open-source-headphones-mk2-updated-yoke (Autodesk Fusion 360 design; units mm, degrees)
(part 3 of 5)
sketch "Sketch1" plane through (0, 0, 1.5) normal (0, 0, 1) x axis (-1, 0, 0)
  line L1 (-6.5, -117.4019) -> (-9.9868, -115.3888)
  line L2 (-1, -130.9545) -> (-1, -126.9282)
  line L3 (-1, -107.0385) -> (-1, -103.0294)
  line L4 (-14.1969, -110.6487) -> (-10.725, -112.6532)
  line L5 (5.5, -115.6699) -> (8.9868, -113.6567)
  line L6 (-8.9868, -113.6567) -> (-5.5, -115.6699)
  line L7 (1, -132.9615) -> (1, -136.9706)
  line L8 (14.1969, -129.3513) -> (10.725, -127.3468)
  line L9 (11.725, -125.6147) -> (15.1969, -127.6193)
  line L10 (15.1969, -112.3807) -> (11.725, -114.3853)
  line L11 (-11.725, -114.3853) -> (-15.1969, -112.3807)
  line L12 (-15.1969, -127.6193) -> (-11.725, -125.6147)
  line L13 (-10.725, -127.3468) -> (-14.1969, -129.3513)
  line L14 (-1, -136.9706) -> (-1, -132.9615)
  line L15 (10.725, -112.6532) -> (14.1969, -110.6487)
  line L16 (1, -103.0294) -> (1, -107.0385)
  line L17 (1, -126.9282) -> (1, -130.9545)
  line L18 (9.9868, -115.3888) -> (6.5, -117.4019)
  line L19 (-16.1795, -137.7263) -> (-12.9621, -133.8919)
  line L20 (-11.43, -135.1775) -> (-14.6475, -139.0119)
  line L21 (-1, -143.9792) -> (-1, -138.9737)
  line L22 (1, -138.9737) -> (1, -143.9792)
  line L23 (14.6475, -139.0119) -> (11.43, -135.1775)
  line L24 (12.9621, -133.8919) -> (16.1795, -137.7263)
  line L25 (23.4412, -125.1487) -> (18.5118, -124.2796)
  line L26 (18.8591, -122.3099) -> (23.7885, -123.1791)
  line L27 (21.2666, -108.8764) -> (16.9317, -111.3792)
  line L28 (15.9317, -109.6471) -> (20.2666, -107.1444)
  line L29 (9.141, -97.809) -> (7.4291, -102.5126)
  line L30 (5.5497, -101.8286) -> (7.2617, -97.1249)
  line L31 (-7.2617, -97.1249) -> (-5.5497, -101.8286)
  line L32 (-7.4291, -102.5126) -> (-9.141, -97.809)
  line L33 (-20.2666, -107.1444) -> (-15.9317, -109.6471)
  line L34 (-16.9317, -111.3792) -> (-21.2666, -108.8764)
  line L35 (-23.7885, -123.1791) -> (-18.8591, -122.3099)
  line L36 (-18.5118, -124.2796) -> (-23.4412, -125.1487)
  arc A1 centre (0, -120) radius 7 clockwise from (-1, -126.9282) to (-6.5, -117.4019)
  arc A2 centre (0, -120) radius 11 clockwise from (-1, -130.9545) to (-9.9868, -115.3888)
  arc A3 centre (0, -120) radius 13 clockwise from (-10.725, -112.6532) to (-1, -107.0385)
  arc A4 centre (0, -120) radius 17 clockwise from (-14.1969, -110.6487) to (-1, -103.0294)
  circle C1 centre (0, -120) radius 5
  arc A5 centre (0, -120) radius 7 clockwise from (-5.5, -115.6699) to (5.5, -115.6699)
  arc A6 centre (0, -120) radius 11 clockwise from (-8.9868, -113.6567) to (8.9868, -113.6567)
  arc A7 centre (0, -120) radius 13 clockwise from (10.725, -127.3468) to (1, -132.9615)
  arc A8 centre (0, -120) radius 17 clockwise from (14.1969, -129.3513) to (1, -136.9706)
  arc A9 centre (0, -120) radius 17 clockwise from (15.1969, -112.3807) to (15.1969, -127.6193)
  arc A10 centre (0, -120) radius 13 clockwise from (11.725, -114.3853) to (11.725, -125.6147)
  arc A11 centre (0, -120) radius 17 clockwise from (-15.1969, -127.6193) to (-15.1969, -112.3807)
  arc A12 centre (0, -120) radius 13 clockwise from (-11.725, -125.6147) to (-11.725, -114.3853)
  arc A13 centre (0, -120) radius 17 clockwise from (-1, -136.9706) to (-14.1969, -129.3513)
  arc A14 centre (0, -120) radius 13 clockwise from (-1, -132.9615) to (-10.725, -127.3468)
  arc A15 centre (0, -120) radius 17 clockwise from (1, -103.0294) to (14.1969, -110.6487)
  arc A16 centre (0, -120) radius 13 clockwise from (1, -107.0385) to (10.725, -112.6532)
  arc A17 centre (0, -120) radius 7 clockwise from (6.5, -117.4019) to (1, -126.9282)
  arc A18 centre (0, -120) radius 11 clockwise from (9.9868, -115.3888) to (1, -130.9545)
  arc A19 centre (0, -120) radius 19 clockwise from (-12.9621, -133.8919) to (-18.5118, -124.2796)
  arc A20 centre (0, -120) radius 24 clockwise from (-14.6475, -139.0119) to (-16.1795, -137.7263)
  arc A21 centre (0, -120) radius 19 clockwise from (-1, -138.9737) to (-11.43, -135.1775)
  arc A22 centre (0, -120) radius 24 clockwise from (1, -143.9792) to (-1, -143.9792)
  arc A23 centre (0, -120) radius 19 clockwise from (11.43, -135.1775) to (1, -138.9737)
  arc A24 centre (0, -120) radius 24 clockwise from (16.1795, -137.7263) to (14.6475, -139.0119)
  arc A25 centre (0, -120) radius 19 clockwise from (18.5118, -124.2796) to (12.9621, -133.8919)
  arc A26 centre (0, -120) radius 24 clockwise from (23.7885, -123.1791) to (23.4412, -125.1487)
  arc A27 centre (0, -120) radius 19 clockwise from (16.9317, -111.3792) to (18.8591, -122.3099)
  arc A28 centre (0, -120) radius 24 clockwise from (20.2666, -107.1444) to (21.2666, -108.8764)
  arc A29 centre (0, -120) radius 19 clockwise from (7.4291, -102.5126) to (15.9317, -109.6471)
  arc A30 centre (0, -120) radius 24 clockwise from (7.2617, -97.1249) to (9.141, -97.809)
  arc A31 centre (0, -120) radius 19 clockwise from (-5.5497, -101.8286) to (5.5497, -101.8286)
  arc A32 centre (0, -120) radius 24 clockwise from (-9.141, -97.809) to (-7.2617, -97.1249)
  arc A33 centre (0, -120) radius 19 clockwise from (-15.9317, -109.6471) to (-7.4291, -102.5126)
  arc A34 centre (0, -120) radius 24 clockwise from (-21.2666, -108.8764) to (-20.2666, -107.1444)
  arc A35 centre (0, -120) radius 19 clockwise from (-18.8591, -122.3099) to (-16.9317, -111.3792)
  arc A36 centre (0, -120) radius 24 clockwise from (-23.4412, -125.1487) to (-23.7885, -123.1791)
  circle C2 centre (0, -120) radius 19
  concentric A1 C2
  dimension "d412" diameter C2 = 38
extrude "Extrude1" cut sketch "Sketch1" profile of L19 A20 L20 L21 A22 L22 L23 A24 L24 L25 A26 L26 L27 A28 L28 L29 A30 L30 L31 A32 L32 L33 A34 L34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 against normal blind 1.5 bodies "Pad Mount (1)"
sketch "Sketch2" plane through (0, 0, 0) normal (0, 0, -1) x axis (1, 0, 0)
  line L1 (9.9868, -115.3888) -> (6.5, -117.4019)
  line L2 (1, -126.9282) -> (1, -130.9545)
  line L3 (1, -103.0294) -> (1, -107.0385)
  line L4 (10.725, -112.6532) -> (14.1969, -110.6487)
  line L5 (-8.9868, -113.6567) -> (-5.5, -115.6699)
  line L6 (5.5, -115.6699) -> (8.9868, -113.6567)
  line L7 (-1, -136.9706) -> (-1, -132.9615)
  line L8 (-10.725, -127.3468) -> (-14.1969, -129.3513)
  line L9 (-11.725, -114.3853) -> (-15.1969, -112.3807)
  line L10 (-15.1969, -127.6193) -> (-11.725, -125.6147)
  line L11 (11.725, -125.6147) -> (15.1969, -127.6193)
  line L12 (15.1969, -112.3807) -> (11.725, -114.3853)
  line L13 (1, -132.9615) -> (1, -136.9706)
  line L14 (14.1969, -129.3513) -> (10.725, -127.3468)
  line L15 (-1, -107.0385) -> (-1, -103.0294)
  line L16 (-14.1969, -110.6487) -> (-10.725, -112.6532)
  line L17 (-1, -130.9545) -> (-1, -126.9282)
  line L18 (-6.5, -117.4019) -> (-9.9868, -115.3888)
  circle C1 centre (0, -120) radius 19
  arc A1 centre (0, -120) radius 11 clockwise from (9.9868, -115.3888) to (1, -130.9545)
  arc A2 centre (0, -120) radius 7 clockwise from (6.5, -117.4019) to (1, -126.9282)
  arc A3 centre (0, -120) radius 17 clockwise from (1, -103.0294) to (14.1969, -110.6487)
  arc A4 centre (0, -120) radius 13 clockwise from (1, -107.0385) to (10.725, -112.6532)
  circle C2 centre (0, -120) radius 5
  arc A5 centre (0, -120) radius 11 clockwise from (-8.9868, -113.6567) to (8.9868, -113.6567)
  arc A6 centre (0, -120) radius 7 clockwise from (-5.5, -115.6699) to (5.5, -115.6699)
  arc A7 centre (0, -120) radius 17 clockwise from (-1, -136.9706) to (-14.1969, -129.3513)
  arc A8 centre (0, -120) radius 13 clockwise from (-1, -132.9615) to (-10.725, -127.3468)
  arc A9 centre (0, -120) radius 17 clockwise from (-15.1969, -127.6193) to (-15.1969, -112.3807)
  arc A10 centre (0, -120) radius 13 clockwise from (-11.725, -125.6147) to (-11.725, -114.3853)
  arc A11 centre (0, -120) radius 17 clockwise from (15.1969, -112.3807) to (15.1969, -127.6193)
  arc A12 centre (0, -120) radius 13 clockwise from (11.725, -114.3853) to (11.725, -125.6147)
  arc A13 centre (0, -120) radius 17 clockwise from (14.1969, -129.3513) to (1, -136.9706)
  arc A14 centre (0, -120) radius 13 clockwise from (10.725, -127.3468) to (1, -132.9615)
  arc A15 centre (0, -120) radius 17 clockwise from (-14.1969, -110.6487) to (-1, -103.0294)
  arc A16 centre (0, -120) radius 13 clockwise from (-10.725, -112.6532) to (-1, -107.0385)
  arc A17 centre (0, -120) radius 11 clockwise from (-1, -130.9545) to (-9.9868, -115.3888)
  arc A18 centre (0, -120) radius 7 clockwise from (-1, -126.9282) to (-6.5, -117.4019)
  circle C3 centre (0, -120) radius 24
  circle C4 centre (0, -120) radius 20.5
  concentric C1 C3
  concentric C1 C4
  dimension "d415" diameter C3 = 48
  dimension "d416" diameter C4 = 41
extrude "Extrude2" add sketch "Sketch2" profile of C3 C4 against normal blind 2.5
extrude "Extrude3" add of existing geometry blind 2.5
extrude "Extrude4" add sketch "Sketch2" profile of C1 C4 against normal blind 2.5 bodies "Pad Mount (1)"
delete_face "DeleteFace1"
extrude "Extrude5" cut of existing geometry blind -4
sketch "Sketch3" plane through (0, 0, 22) normal (0, 0, 1) x axis (-1, 0, 0)
  line L1 (27.3973, -100.8162) -> (24.0432, -103.1648)
  line L2 (24.0432, -136.8352) -> (27.3973, -139.1838)
  line L3 (-8, -87.4692) -> (-8, -96.1036)
  line L4 (8, -96.1036) -> (8, -87.4692)
  line L5 (-27.3973, -139.1838) -> (-24.0432, -136.8352)
  line L6 (-24.0432, -103.1648) -> (-27.3973, -100.8162)
  line L7 (-8, -65.8761) -> (-8, -68.1306)
  line L8 (8, -68.1306) -> (8, -65.8761)
  line L9 (17.2573, -73.968) -> (18.1032, -72.1557)
  line L10 (6, -66.9692) -> (6, -69.7523)
  line L11 (-6, -66.9692) -> (6, -66.9692)
  line L12 (-6, -69.7523) -> (-6, -66.9692)
  line L13 (-18.1032, -72.1557) -> (-17.2573, -73.968)
  line L14 (-15.6326, -145.0174) -> (-17.7523, -148.4096)
  line L15 (17.7523, -148.4096) -> (15.6326, -145.0174)
  line L16 (8, -97) -> (8, -96.1036)
  line L17 (8, -101.1254) -> (8, -97)
  line L18 (-8, -101.1254) -> (-8, -96.1036)
  line L19 (20.5, -120) -> (0, -120)
  line L20 (15.9099, -104.0901) -> (0, -120)
  line L21 (22.5, -120) -> (0, -120)
  line L22 (-15.9099, -104.0901) -> (0, -120)
  line L23 (-22.5, -120) -> (0, -120)
  line L24 (44.7744, -114.5) -> (37, -114.5)
  line L25 (-37, -114.5) -> (-44.7744, -114.5)
  line L26 (-37, -125.5) -> (-37, -114.5)
  line L27 (-44.7744, -125.5) -> (-37, -125.5)
  line L28 (37, -125.5) -> (44.7744, -125.5)
  line L29 (37, -114.5) -> (37, -125.5)
  line L30 (40.4204, -134.6184) -> (31.8667, -135.2833)
  line L31 (40.0904, -135.7159) -> (40.4204, -134.6184)
  line L32 (33.9261, -136.0336) -> (40.0904, -135.7159)
  curve K1 (32.5509, -136.0589) -> (33.9261, -136.0336)
  curve K2 (33.681, -136.8488) -> (32.5509, -136.0589)
  line L33 (38.6244, -140.5917) -> (33.681, -136.8488)
  line L34 (38.3133, -141.6264) -> (38.6244, -140.5917)
  line L35 (31.554, -136.3233) -> (38.3133, -141.6264)
  line L36 (31.8667, -135.2833) -> (31.554, -136.3233)
  line L37 (30.457, -152.0325) -> (25.6804, -148.7507)
  line L38 (29.9007, -152.8421) -> (30.457, -152.0325)
  line L39 (25.1241, -149.5603) -> (29.9007, -152.8421)
  line L40 (25.6804, -148.7507) -> (25.1241, -149.5603)
  line L41 (-27.2839, -159.541) -> (-19.3124, -156.3956)
  line L42 (-28.0551, -158.7007) -> (-27.2839, -159.541)
  line L43 (-24.3746, -150.8793) -> (-28.0551, -158.7007)
  line L44 (-23.5592, -151.7679) -> (-24.3746, -150.8793)
  line L45 (-24.7134, -154.0936) -> (-23.5592, -151.7679)
  line L46 (-22.4517, -156.5582) -> (-24.7134, -154.0936)
  line L47 (-20.0725, -155.5673) -> (-22.4517, -156.5582)
  line L48 (-19.3124, -156.3956) -> (-20.0725, -155.5673)
  line L49 (-35.6785, -142.0432) -> (-30.2699, -139.9615)
  line L50 (-36.0313, -141.1265) -> (-35.6785, -142.0432)
  line L51 (-30.6227, -139.0448) -> (-36.0313, -141.1265)
  line L52 (-30.2699, -139.9615) -> (-30.6227, -139.0448)
  line L53 (-37.736, -142.8351) -> (-36.6818, -142.4293)
  line L54 (-38.0888, -141.9183) -> (-37.736, -142.8351)
  line L55 (-37.0346, -141.5126) -> (-38.0888, -141.9183)
  line L56 (-36.6818, -142.4293) -> (-37.0346, -141.5126)
  line L57 (-18.3117, -159.6909) -> (-17.5657, -160.3171)
  curve K3 (-16.7865, -158.8106) -> (-18.3117, -159.6909)
  curve K4 (-15.133, -159.1979) -> (-16.7865, -158.8106)
  curve K5 (-13.9409, -160.8837) -> (-15.133, -159.1979)
  curve K6 (-14.5331, -163.1512) -> (-13.9409, -160.8837)
  curve K7 (-15.6803, -164.3672) -> (-14.5331, -163.1512)
  curve K8 (-17.0469, -164.7465) -> (-15.6803, -164.3672)
  curve K9 (-18.4019, -164.2975) -> (-17.0469, -164.7465)
  curve K10 (-19.4455, -163.063) -> (-18.4019, -164.2975)
  curve K11 (-19.3628, -161.506) -> (-19.4455, -163.063)
  line L58 (-18.479, -161.8966) -> (-19.3628, -161.506)
  curve K12 (-18.5456, -162.8969) -> (-18.479, -161.8966)
  curve K13 (-17.9988, -163.5965) -> (-18.5456, -162.8969)
  curve K14 (-16.6962, -163.7983) -> (-17.9988, -163.5965)
  curve K15 (-15.3982, -162.6301) -> (-16.6962, -163.7983)
  curve K16 (-14.8606, -160.9594) -> (-15.3982, -162.6301)
  curve K17 (-15.559, -159.8841) -> (-14.8606, -160.9594)
  curve K18 (-16.5638, -159.6624) -> (-15.559, -159.8841)
  curve K19 (-17.5657, -160.3171) -> (-16.5638, -159.6624)
  curve K20 (29.3301, -142.3161) -> (29.4979, -143.5426)
  curve K21 (29.5989, -141.2495) -> (29.3301, -142.3161)
  curve K22 (30.6252, -140.1009) -> (29.5989, -141.2495)
  curve K23 (31.923, -140.1206) -> (30.6252, -140.1009)
  curve K24 (32.5534, -140.6155) -> (31.923, -140.1206)
  curve K25 (32.8611, -141.3096) -> (32.5534, -140.6155)
  curve K26 (32.8658, -142.0862) -> (32.8611, -141.3096)
  curve K27 (32.6431, -142.9432) -> (32.8658, -142.0862)
  curve K28 (32.2353, -144.68) -> (32.6431, -142.9432)
  curve K29 (32.4671, -144.7899) -> (32.2353, -144.68)
  curve K30 (33.3528, -144.882) -> (32.4671, -144.7899)
  curve K31 (34.1141, -143.9973) -> (33.3528, -144.882)
  curve K32 (34.3111, -142.9643) -> (34.1141, -143.9973)
  curve K33 (33.7266, -142.1671) -> (34.3111, -142.9643)
  line L59 (34.239, -141.3443) -> (33.7266, -142.1671)
  curve K34 (34.9714, -142.145) -> (34.239, -141.3443)
  curve K35 (35.1493, -143.1756) -> (34.9714, -142.145)
  curve K36 (34.7981, -144.4594) -> (35.1493, -143.1756)
  curve K37 (34.1454, -145.4885) -> (34.7981, -144.4594)
  curve K38 (33.4655, -145.9312) -> (34.1454, -145.4885)
  curve K39 (32.7305, -145.9366) -> (33.4655, -145.9312)
  curve K40 (31.8838, -145.6108) -> (32.7305, -145.9366)
  line L60 (30.6887, -145.0751) -> (31.8838, -145.6108)
  curve K41 (29.082, -144.4236) -> (30.6887, -145.0751)
  curve K42 (28.3455, -144.3655) -> (29.082, -144.4236)
  line L61 (28.7652, -143.4294) -> (28.3455, -144.3655)
  curve K43 (29.4979, -143.5426) -> (28.7652, -143.4294)
  curve K44 (-36.4141, -138.56) -> (-33.8745, -138.7564)
  curve K45 (-37.5395, -136.9883) -> (-36.4141, -138.56)
  curve K46 (-37.3306, -134.894) -> (-37.5395, -136.9883)
  curve K47 (-35.4632, -133.5636) -> (-37.3306, -134.894)
  curve K48 (-33.6794, -133.3966) -> (-35.4632, -133.5636)
  curve K49 (-32.4511, -134.0579) -> (-33.6794, -133.3966)
  curve K50 (-31.7211, -135.3037) -> (-32.4511, -134.0579)
  curve K51 (-31.9236, -137.4104) -> (-31.7211, -135.3037)
  curve K52 (-33.8745, -138.7564) -> (-31.9236, -137.4104)
  line L62 (20.5824, -155.057) -> (19.8923, -155.6522)
  line L63 (25.8075, -161.1149) -> (20.5824, -155.057)
  line L64 (25.0636, -161.7565) -> (25.8075, -161.1149)
  line L65 (23.1996, -159.5953) -> (25.0636, -161.7565)
  curve K53 (22.5068, -161.2234) -> (23.1996, -159.5953)
  curve K54 (21.5994, -161.7213) -> (22.5068, -161.2234)
  curve K55 (20.6088, -161.7759) -> (21.5994, -161.7213)
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  point P10 (8, -96.1036)
  point P40 (8, -96.1036)
  point P9 (-8, -96.1036)
  point P43 (-8, -96.1036)
  point P4 (0, -120)
  point P46 (0, -120)
  point P49 (0, -120)
  point P45 (0, -120)
  point P52 (0, -120)
  coincident P10 P40
  parallel L4 L17
  coincident P9 P43
  parallel L3 L18
  horizontal L19
  coincident P4 P46
  horizontal L21
  coincident P4 P49
  horizontal L23
  coincident P45 P52
  dimension "d425" diameter = 41
  dimension "d426" diameter = 32
  dimension "d428" diameter = 45
  dimension "d429" angle L20 L21 = 45
  dimension "d430" angle L22 L23 = 45
extrude "Extrude6" add sketch "Sketch3" against normal blind 2
extrude "Extrude7" add sketch "Sketch3" along normal blind 4
chamfer "Chamfer1" distance 4.5 Rotate Angle 40
chamfer "Chamfer2" distance 4 Rotate Angle 45
copy_paste_bodies "CopyPasteBodies2"
move "Move1"
delete_face "DeleteFace2"
extrude "Extrude8" cut of existing geometry blind -4
offset_faces "OffsetFaces1" distance 1
offset_faces "OffsetFaces2" distance -1
delete_face "DeleteFace3"
offset_faces "OffsetFaces3" distance 1
offset_faces "OffsetFaces4" distance -1
sketch "Sketch4" plane through (0, 0, 22) normal (0, 0, 1) x axis (-1, 0, 0)
  line L1 (-127.3973, -19.1838) -> (-124.8888, -17.4274)
  line L2 (-124.8888, 17.4274) -> (-127.3973, 19.1838)
  curve K1 (-124.8888, 17.4274) -> (-124.8888, -17.4274)
  line L3 (-115.6326, -25.0174) -> (-117.7523, -28.4096)
  line L4 (-82.2477, -28.4096) -> (-84.3674, -25.0174)
  line L5 (-108, 54.1239) -> (-108, 51.8694)
  line L6 (-92, 51.8694) -> (-92, 54.1239)
  line L7 (-82.7427, 46.032) -> (-81.8968, 47.8443)
  line L8 (-94, 53.0308) -> (-94, 50.2477)
  line L9 (-106, 53.0308) -> (-94, 53.0308)
  line L10 (-106, 50.2477) -> (-106, 53.0308)
  line L11 (-118.1032, 47.8443) -> (-117.2573, 46.032)
  line L12 (-72.6027, 19.1838) -> (-75.1112, 17.4274)
  line L13 (-75.1112, -17.4274) -> (-72.6027, -19.1838)
  curve K2 (-75.1112, -17.4274) -> (-75.1112, 17.4274)
  line L14 (-108, 32.5308) -> (-108, 24.9487)
  line L15 (-92, 24.9487) -> (-92, 32.5308)
  line L16 (-79.706, 20.294) -> (-100, 0)
  line L17 (-71.3, 0) -> (-100, 0)
  line L18 (-120.294, 20.294) -> (-100, 0)
  line L19 (-128.7, 0) -> (-100, 0)
  line L20 (-55.2256, 5.5) -> (-63, 5.5)
  line L21 (-137, 5.5) -> (-144.7744, 5.5)
  line L22 (-137, -5.5) -> (-137, 5.5)
  line L23 (-144.7744, -5.5) -> (-137, -5.5)
  line L24 (-63, -5.5) -> (-55.2256, -5.5)
  line L25 (-63, 5.5) -> (-63, -5.5)
  line L26 (-59.5796, -14.6184) -> (-68.1333, -15.2833)
  line L27 (-59.9096, -15.7159) -> (-59.5796, -14.6184)
  line L28 (-66.0739, -16.0336) -> (-59.9096, -15.7159)
  curve K3 (-67.4491, -16.0589) -> (-66.0739, -16.0336)
  curve K4 (-66.319, -16.8488) -> (-67.4491, -16.0589)
  line L29 (-61.3756, -20.5917) -> (-66.319, -16.8488)
  line L30 (-61.6867, -21.6264) -> (-61.3756, -20.5917)
  line L31 (-68.446, -16.3233) -> (-61.6867, -21.6264)
  line L32 (-68.1333, -15.2833) -> (-68.446, -16.3233)
  line L33 (-69.543, -32.0325) -> (-74.3196, -28.7507)
  line L34 (-70.0993, -32.8421) -> (-69.543, -32.0325)
  line L35 (-74.8759, -29.5603) -> (-70.0993, -32.8421)
  line L36 (-74.3196, -28.7507) -> (-74.8759, -29.5603)
  line L37 (-127.2839, -39.541) -> (-119.3124, -36.3956)
  line L38 (-128.0551, -38.7007) -> (-127.2839, -39.541)
  line L39 (-124.3746, -30.8793) -> (-128.0551, -38.7007)
  line L40 (-123.5592, -31.7679) -> (-124.3746, -30.8793)
  line L41 (-124.7134, -34.0936) -> (-123.5592, -31.7679)
  line L42 (-122.4517, -36.5582) -> (-124.7134, -34.0936)
  line L43 (-120.0725, -35.5673) -> (-122.4517, -36.5582)
  line L44 (-119.3124, -36.3956) -> (-120.0725, -35.5673)
  line L45 (-135.6785, -22.0432) -> (-130.2699, -19.9615)
  line L46 (-136.0313, -21.1265) -> (-135.6785, -22.0432)
  line L47 (-130.6227, -19.0448) -> (-136.0313, -21.1265)
  line L48 (-130.2699, -19.9615) -> (-130.6227, -19.0448)
  line L49 (-137.736, -22.8351) -> (-136.6818, -22.4293)
  line L50 (-138.0888, -21.9183) -> (-137.736, -22.8351)
  line L51 (-137.0346, -21.5126) -> (-138.0888, -21.9183)
  line L52 (-136.6818, -22.4293) -> (-137.0346, -21.5126)
  line L53 (-118.3117, -39.6909) -> (-117.5657, -40.3171)
  curve K5 (-116.7865, -38.8106) -> (-118.3117, -39.6909)
  curve K6 (-115.133, -39.1979) -> (-116.7865, -38.8106)
  curve K7 (-113.9409, -40.8837) -> (-115.133, -39.1979)
  curve K8 (-114.5331, -43.1512) -> (-113.9409, -40.8837)
  curve K9 (-115.6803, -44.3672) -> (-114.5331, -43.1512)
  curve K10 (-117.0469, -44.7465) -> (-115.6803, -44.3672)
  curve K11 (-118.4019, -44.2975) -> (-117.0469, -44.7465)
  curve K12 (-119.4455, -43.063) -> (-118.4019, -44.2975)
  curve K13 (-119.3628, -41.506) -> (-119.4455, -43.063)
  line L54 (-118.479, -41.8966) -> (-119.3628, -41.506)
  curve K14 (-118.5456, -42.8969) -> (-118.479, -41.8966)
  curve K15 (-117.9988, -43.5965) -> (-118.5456, -42.8969)
  curve K16 (-116.6962, -43.7983) -> (-117.9988, -43.5965)
  curve K17 (-115.3982, -42.6301) -> (-116.6962, -43.7983)
  curve K18 (-114.8606, -40.9594) -> (-115.3982, -42.6301)
  curve K19 (-115.559, -39.8841) -> (-114.8606, -40.9594)
  curve K20 (-116.5638, -39.6624) -> (-115.559, -39.8841)
  curve K21 (-117.5657, -40.3171) -> (-116.5638, -39.6624)
  curve K22 (-70.6699, -22.3161) -> (-70.5021, -23.5426)
  curve K23 (-70.4011, -21.2495) -> (-70.6699, -22.3161)
  curve K24 (-69.3748, -20.1009) -> (-70.4011, -21.2495)
  curve K25 (-68.077, -20.1206) -> (-69.3748, -20.1009)
  curve K26 (-67.4466, -20.6155) -> (-68.077, -20.1206)
  curve K27 (-67.1389, -21.3096) -> (-67.4466, -20.6155)
  curve K28 (-67.1342, -22.0862) -> (-67.1389, -21.3096)
  curve K29 (-67.3569, -22.9432) -> (-67.1342, -22.0862)
  curve K30 (-67.7647, -24.68) -> (-67.3569, -22.9432)
  curve K31 (-67.5329, -24.7899) -> (-67.7647, -24.68)
  curve K32 (-66.6472, -24.882) -> (-67.5329, -24.7899)
  curve K33 (-65.8859, -23.9973) -> (-66.6472, -24.882)
  curve K34 (-65.6889, -22.9643) -> (-65.8859, -23.9973)
  curve K35 (-66.2734, -22.1671) -> (-65.6889, -22.9643)
  line L55 (-65.761, -21.3443) -> (-66.2734, -22.1671)
  curve K36 (-65.0286, -22.145) -> (-65.761, -21.3443)
  curve K37 (-64.8507, -23.1756) -> (-65.0286, -22.145)
  curve K38 (-65.2019, -24.4594) -> (-64.8507, -23.1756)
  curve K39 (-65.8546, -25.4885) -> (-65.2019, -24.4594)
  curve K40 (-66.5345, -25.9312) -> (-65.8546, -25.4885)
  curve K41 (-67.2695, -25.9366) -> (-66.5345, -25.9312)
  curve K42 (-68.1162, -25.6108) -> (-67.2695, -25.9366)
  line L56 (-69.3113, -25.0751) -> (-68.1162, -25.6108)
  curve K43 (-70.918, -24.4236) -> (-69.3113, -25.0751)
  curve K44 (-71.6545, -24.3655) -> (-70.918, -24.4236)
  line L57 (-71.2348, -23.4294) -> (-71.6545, -24.3655)
  curve K45 (-70.5021, -23.5426) -> (-71.2348, -23.4294)
  curve K46 (-136.4141, -18.56) -> (-133.8745, -18.7564)
  curve K47 (-137.5395, -16.9883) -> (-136.4141, -18.56)
  curve K48 (-137.3306, -14.894) -> (-137.5395, -16.9883)
  curve K49 (-135.4632, -13.5636) -> (-137.3306, -14.894)
  curve K50 (-133.6794, -13.3966) -> (-135.4632, -13.5636)
  curve K51 (-132.4511, -14.0579) -> (-133.6794, -13.3966)
  curve K52 (-131.7211, -15.3037) -> (-132.4511, -14.0579)
  curve K53 (-131.9236, -17.4104) -> (-131.7211, -15.3037)
  curve K54 (-133.8745, -18.7564) -> (-131.9236, -17.4104)
  line L58 (-79.4176, -35.057) -> (-80.1077, -35.6522)
  line L59 (-74.1925, -41.1149) -> (-79.4176, -35.057)
  line L60 (-74.9364, -41.7565) -> (-74.1925, -41.1149)
  line L61 (-76.8004, -39.5953) -> (-74.9364, -41.7565)
  curve K55 (-77.4932, -41.2234) -> (-76.8004, -39.5953)
  curve K56 (-78.4006, -41.7213) -> (-77.4932, -41.2234)
  curve K57 (-79.3912, -41.7759) -> (-78.4006, -41.7213)
  curve K58 (-80.3718, -41.3785) -> (-79.3912, -41.7759)
  curve K59 (-81.2739, -40.6) -> (-80.3718, -41.3785)
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  point P35 (-100, 0)
  point P38 (-100, 0)
  point P5 (-100, 0)
  point P41 (-100, 0)
  horizontal L17
  coincident P35 P38
  horizontal L19
  coincident P5 P41
  dimension "d445" diameter = 42
  dimension "d446" diameter = 52.4
  dimension "d449" diameter = 57.4
  dimension "d452" angle L16 L17 = 45
  dimension "d453" angle L18 L19 = 45
extrude "Extrude9" add sketch "Sketch4" against normal blind 2
extrude "Extrude10" add sketch "Sketch4" along normal blind 5
chamfer "Chamfer3" distance 5.2 Rotate Angle 40
chamfer "Chamfer4" distance 5 Rotate Angle 45
offset_faces "OffsetFaces5" distance 5
offset_faces "OffsetFaces8" distance 1
offset_faces "OffsetFaces9" distance -1
copy_paste_bodies "CopyPasteBodies3"
move "Move2"
copy_paste_bodies "CopyPasteBodies4"
move "Move3"
delete_face "DeleteFace4"
extrude "Extrude11" cut of existing geometry blind -4
offset_faces "OffsetFaces10" distance 3
offset_faces "OffsetFaces11" distance 2.5
offset_faces "OffsetFaces12" distance 3
offset_faces "OffsetFaces13" distance 2.5
sketch "Sketch5" plane through (0, 0, 22) normal (0, 0, 1) x axis (-1, 0, 0)
  line L1 (-72.6027, -100.8162) -> (-75.9568, -103.1648)
  line L2 (-75.9568, -136.8352) -> (-72.6027, -139.1838)
  line L3 (-108, -87.4692) -> (-108, -99.2915)
  line L4 (-92, -99.2915) -> (-92, -87.4692)
  line L5 (-127.3973, -139.1838) -> (-124.0432, -136.8352)
  line L6 (-124.0432, -103.1648) -> (-127.3973, -100.8162)
  line L7 (-108, -65.8761) -> (-108, -68.1306)
  line L8 (-92, -68.1306) -> (-92, -65.8761)
  line L9 (-82.7427, -73.968) -> (-81.8968, -72.1557)
  line L10 (-94, -66.9692) -> (-94, -69.7523)
  line L11 (-106, -66.9692) -> (-94, -66.9692)
  line L12 (-106, -69.7523) -> (-106, -66.9692)
  line L13 (-118.1032, -72.1557) -> (-117.2573, -73.968)
  line L14 (-115.6326, -145.0174) -> (-117.7523, -148.4096)
  line L15 (-82.2477, -148.4096) -> (-84.3674, -145.0174)
  line L16 (-82.888, -102.888) -> (-100, -120)
  line L17 (-75.8, -120) -> (-100, -120)
  line L18 (-117.112, -102.888) -> (-100, -120)
  line L19 (-124.2, -120) -> (-100, -120)
  line L20 (-55.2256, -114.5) -> (-63, -114.5)
  line L21 (-137, -114.5) -> (-144.7744, -114.5)
  line L22 (-137, -125.5) -> (-137, -114.5)
  line L23 (-144.7744, -125.5) -> (-137, -125.5)
  line L24 (-63, -125.5) -> (-55.2256, -125.5)
  line L25 (-63, -114.5) -> (-63, -125.5)
  line L26 (-59.5796, -134.6184) -> (-68.1333, -135.2833)
  line L27 (-59.9096, -135.7159) -> (-59.5796, -134.6184)
  line L28 (-66.0739, -136.0336) -> (-59.9096, -135.7159)
  curve K1 (-67.4491, -136.0589) -> (-66.0739, -136.0336)
  curve K2 (-66.319, -136.8488) -> (-67.4491, -136.0589)
  line L29 (-61.3756, -140.5917) -> (-66.319, -136.8488)
  line L30 (-61.6867, -141.6264) -> (-61.3756, -140.5917)
  line L31 (-68.446, -136.3233) -> (-61.6867, -141.6264)
  line L32 (-68.1333, -135.2833) -> (-68.446, -136.3233)
  line L33 (-69.543, -152.0325) -> (-74.3196, -148.7507)
  line L34 (-70.0993, -152.8421) -> (-69.543, -152.0325)
  line L35 (-74.8759, -149.5603) -> (-70.0993, -152.8421)
  line L36 (-74.3196, -148.7507) -> (-74.8759, -149.5603)
  line L37 (-127.2839, -159.541) -> (-119.3124, -156.3956)
  line L38 (-128.0551, -158.7007) -> (-127.2839, -159.541)
  line L39 (-124.3746, -150.8793) -> (-128.0551, -158.7007)
  line L40 (-123.5592, -151.7679) -> (-124.3746, -150.8793)
  line L41 (-124.7134, -154.0936) -> (-123.5592, -151.7679)
  line L42 (-122.4517, -156.5582) -> (-124.7134, -154.0936)
  line L43 (-120.0725, -155.5673) -> (-122.4517, -156.5582)
  line L44 (-119.3124, -156.3956) -> (-120.0725, -155.5673)
  line L45 (-135.6785, -142.0432) -> (-130.2699, -139.9615)
  line L46 (-136.0313, -141.1265) -> (-135.6785, -142.0432)
  line L47 (-130.6227, -139.0448) -> (-136.0313, -141.1265)
  line L48 (-130.2699, -139.9615) -> (-130.6227, -139.0448)
  line L49 (-137.736, -142.8351) -> (-136.6818, -142.4293)
  line L50 (-138.0888, -141.9183) -> (-137.736, -142.8351)
  line L51 (-137.0346, -141.5126) -> (-138.0888, -141.9183)
  line L52 (-136.6818, -142.4293) -> (-137.0346, -141.5126)
  line L53 (-118.3117, -159.6909) -> (-117.5657, -160.3171)
  curve K3 (-116.7865, -158.8106) -> (-118.3117, -159.6909)
  curve K4 (-115.133, -159.1979) -> (-116.7865, -158.8106)
  curve K5 (-113.9409, -160.8837) -> (-115.133, -159.1979)
  curve K6 (-114.5331, -163.1512) -> (-113.9409, -160.8837)
  curve K7 (-115.6803, -164.3672) -> (-114.5331, -163.1512)
  curve K8 (-117.0469, -164.7465) -> (-115.6803, -164.3672)
  curve K9 (-118.4019, -164.2975) -> (-117.0469, -164.7465)
  curve K10 (-119.4455, -163.063) -> (-118.4019, -164.2975)
  curve K11 (-119.3628, -161.506) -> (-119.4455, -163.063)
  line L54 (-118.479, -161.8966) -> (-119.3628, -161.506)
  curve K12 (-118.5456, -162.8969) -> (-118.479, -161.8966)
  curve K13 (-117.9988, -163.5965) -> (-118.5456, -162.8969)
  curve K14 (-116.6962, -163.7983) -> (-117.9988, -163.5965)
  curve K15 (-115.3982, -162.6301) -> (-116.6962, -163.7983)
  curve K16 (-114.8606, -160.9594) -> (-115.3982, -162.6301)
  curve K17 (-115.559, -159.8841) -> (-114.8606, -160.9594)
  curve K18 (-116.5638, -159.6624) -> (-115.559, -159.8841)
  curve K19 (-117.5657, -160.3171) -> (-116.5638, -159.6624)
  curve K20 (-70.6699, -142.3161) -> (-70.5021, -143.5426)
  curve K21 (-70.4011, -141.2495) -> (-70.6699, -142.3161)
  curve K22 (-69.3748, -140.1009) -> (-70.4011, -141.2495)
  curve K23 (-68.077, -140.1206) -> (-69.3748, -140.1009)
  curve K24 (-67.4466, -140.6155) -> (-68.077, -140.1206)
  curve K25 (-67.1389, -141.3096) -> (-67.4466, -140.6155)
  curve K26 (-67.1342, -142.0862) -> (-67.1389, -141.3096)
  curve K27 (-67.3569, -142.9432) -> (-67.1342, -142.0862)
  curve K28 (-67.7647, -144.68) -> (-67.3569, -142.9432)
  curve K29 (-67.5329, -144.7899) -> (-67.7647, -144.68)
  curve K30 (-66.6472, -144.882) -> (-67.5329, -144.7899)
  curve K31 (-65.8859, -143.9973) -> (-66.6472, -144.882)
  curve K32 (-65.6889, -142.9643) -> (-65.8859, -143.9973)
  curve K33 (-66.2734, -142.1671) -> (-65.6889, -142.9643)
  line L55 (-65.761, -141.3443) -> (-66.2734, -142.1671)
  curve K34 (-65.0286, -142.145) -> (-65.761, -141.3443)
  curve K35 (-64.8507, -143.1756) -> (-65.0286, -142.145)
  curve K36 (-65.2019, -144.4594) -> (-64.8507, -143.1756)
  curve K37 (-65.8546, -145.4885) -> (-65.2019, -144.4594)
  curve K38 (-66.5345, -145.9312) -> (-65.8546, -145.4885)
  curve K39 (-67.2695, -145.9366) -> (-66.5345, -145.9312)
  curve K40 (-68.1162, -145.6108) -> (-67.2695, -145.9366)
  line L56 (-69.3113, -145.0751) -> (-68.1162, -145.6108)
  curve K41 (-70.918, -144.4236) -> (-69.3113, -145.0751)
  curve K42 (-71.6545, -144.3655) -> (-70.918, -144.4236)
  line L57 (-71.2348, -143.4294) -> (-71.6545, -144.3655)
  curve K43 (-70.5021, -143.5426) -> (-71.2348, -143.4294)
  curve K44 (-136.4141, -138.56) -> (-133.8745, -138.7564)
  curve K45 (-137.5395, -136.9883) -> (-136.4141, -138.56)
  curve K46 (-137.3306, -134.894) -> (-137.5395, -136.9883)
  curve K47 (-135.4632, -133.5636) -> (-137.3306, -134.894)
  curve K48 (-133.6794, -133.3966) -> (-135.4632, -133.5636)
  curve K49 (-132.4511, -134.0579) -> (-133.6794, -133.3966)
  curve K50 (-131.7211, -135.3037) -> (-132.4511, -134.0579)
  curve K51 (-131.9236, -137.4104) -> (-131.7211, -135.3037)
  curve K52 (-133.8745, -138.7564) -> (-131.9236, -137.4104)
  line L58 (-79.4176, -155.057) -> (-80.1077, -155.6522)
  line L59 (-74.1925, -161.1149) -> (-79.4176, -155.057)
  line L60 (-74.9364, -161.7565) -> (-74.1925, -161.1149)
  line L61 (-76.8004, -159.5953) -> (-74.9364, -161.7565)
  curve K53 (-77.4932, -161.2234) -> (-76.8004, -159.5953)
  curve K54 (-78.4006, -161.7213) -> (-77.4932, -161.2234)
  curve K55 (-79.3912, -161.7759) -> (-78.4006, -161.7213)
  curve K56 (-80.3718, -161.3785) -> (-79.3912, -161.7759)
  curve K57 (-81.2739, -160.6) -> (-80.3718, -161.3785)
  curve K58 (-82.2201, -158.375) -> (-81.2739, -160.6)
  curve K59 (-81.4123, -156.6045) -> (-82.2201, -158.375)
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  point P4 (-100, -120)
  point P41 (-100, -120)
  point P40 (-100, -120)
  point P44 (-100, -120)
  horizontal L17
  coincident P4 P41
  horizontal L19
  coincident P40 P44
  dimension "d471" diameter = 48.4
  dimension "d472" diameter = 36
  dimension "d473" angle L16 L17 = 45
  dimension "d474" angle L18 L19 = 45
extrude "Extrude12" add sketch "Sketch5" along normal blind 4
chamfer "Chamfer5" distance 4.2 Rotate Angle 40
chamfer "Chamfer6" distance 4 Rotate Angle 45
sketch "Sketch6" plane through (0, 0, 22) normal (0, 0, 1) x axis (-1, 0, 0)
  line L1 (-172.6027, -100.8162) -> (-175.9568, -103.1648)
  line L2 (-175.9568, -136.8352) -> (-172.6027, -139.1838)
  line L3 (-208, -87.4692) -> (-208, -98.7564)
  line L4 (-192, -98.7564) -> (-192, -87.4692)
  line L5 (-227.3973, -139.1838) -> (-224.0432, -136.8352)
  line L6 (-224.0432, -103.1648) -> (-227.3973, -100.8162)
  line L7 (-208, -65.8761) -> (-208, -68.1306)
  line L8 (-192, -68.1306) -> (-192, -65.8761)
  line L9 (-182.7427, -73.968) -> (-181.8968, -72.1557)
  line L10 (-194, -66.9692) -> (-194, -69.7523)
  line L11 (-206, -66.9692) -> (-194, -66.9692)
  line L12 (-206, -69.7523) -> (-206, -66.9692)
  line L13 (-218.1032, -72.1557) -> (-217.2573, -73.968)
  line L14 (-215.6326, -145.0174) -> (-217.7523, -148.4096)
  line L15 (-182.2477, -148.4096) -> (-184.3674, -145.0174)
  line L16 (-182.5345, -102.5345) -> (-200, -120)
  line L17 (-175.3, -120) -> (-200, -120)
  line L18 (-217.4655, -102.5345) -> (-200, -120)
  line L19 (-224.7, -120) -> (-200, -120)
  line L20 (-155.2256, -114.5) -> (-163, -114.5)
  line L21 (-237, -114.5) -> (-244.7744, -114.5)
  line L22 (-237, -125.5) -> (-237, -114.5)
  line L23 (-244.7744, -125.5) -> (-237, -125.5)
  line L24 (-163, -125.5) -> (-155.2256, -125.5)
  line L25 (-163, -114.5) -> (-163, -125.5)
  line L26 (-159.5796, -134.6184) -> (-168.1333, -135.2833)
  line L27 (-159.9096, -135.7159) -> (-159.5796, -134.6184)
  line L28 (-166.0739, -136.0336) -> (-159.9096, -135.7159)
  curve K1 (-167.4491, -136.0589) -> (-166.0739, -136.0336)
  curve K2 (-166.319, -136.8488) -> (-167.4491, -136.0589)
  line L29 (-161.3756, -140.5917) -> (-166.319, -136.8488)
  line L30 (-161.6867, -141.6264) -> (-161.3756, -140.5917)
  line L31 (-168.446, -136.3233) -> (-161.6867, -141.6264)
  line L32 (-168.1333, -135.2833) -> (-168.446, -136.3233)
  line L33 (-169.543, -152.0325) -> (-174.3196, -148.7507)
  line L34 (-170.0993, -152.8421) -> (-169.543, -152.0325)
  line L35 (-174.8759, -149.5603) -> (-170.0993, -152.8421)
  line L36 (-174.3196, -148.7507) -> (-174.8759, -149.5603)
  line L37 (-227.2839, -159.541) -> (-219.3124, -156.3956)
  line L38 (-228.0551, -158.7007) -> (-227.2839, -159.541)
  line L39 (-224.3746, -150.8793) -> (-228.0551, -158.7007)
  line L40 (-223.5592, -151.7679) -> (-224.3746, -150.8793)
  line L41 (-224.7134, -154.0936) -> (-223.5592, -151.7679)
  line L42 (-222.4517, -156.5582) -> (-224.7134, -154.0936)
  line L43 (-220.0725, -155.5673) -> (-222.4517, -156.5582)
  line L44 (-219.3124, -156.3956) -> (-220.0725, -155.5673)
  line L45 (-235.6785, -142.0432) -> (-230.2699, -139.9615)
  line L46 (-236.0313, -141.1265) -> (-235.6785, -142.0432)
  line L47 (-230.6227, -139.0448) -> (-236.0313, -141.1265)
  line L48 (-230.2699, -139.9615) -> (-230.6227, -139.0448)
  line L49 (-237.736, -142.8351) -> (-236.6818, -142.4293)
  line L50 (-238.0888, -141.9183) -> (-237.736, -142.8351)
  line L51 (-237.0346, -141.5126) -> (-238.0888, -141.9183)
  line L52 (-236.6818, -142.4293) -> (-237.0346, -141.5126)
  line L53 (-218.3117, -159.6909) -> (-217.5657, -160.3171)
  curve K3 (-216.7865, -158.8106) -> (-218.3117, -159.6909)
  curve K4 (-215.133, -159.1979) -> (-216.7865, -158.8106)
  curve K5 (-213.9409, -160.8837) -> (-215.133, -159.1979)
  curve K6 (-214.5331, -163.1512) -> (-213.9409, -160.8837)
  curve K7 (-215.6803, -164.3672) -> (-214.5331, -163.1512)
  curve K8 (-217.0469, -164.7465) -> (-215.6803, -164.3672)
  curve K9 (-218.4019, -164.2975) -> (-217.0469, -164.7465)
  curve K10 (-219.4455, -163.063) -> (-218.4019, -164.2975)
  curve K11 (-219.3628, -161.506) -> (-219.4455, -163.063)
  line L54 (-218.479, -161.8966) -> (-219.3628, -161.506)
  curve K12 (-218.5456, -162.8969) -> (-218.479, -161.8966)
  curve K13 (-217.9988, -163.5965) -> (-218.5456, -162.8969)
  curve K14 (-216.6962, -163.7983) -> (-217.9988, -163.5965)
  curve K15 (-215.3982, -162.6301) -> (-216.6962, -163.7983)
  curve K16 (-214.8606, -160.9594) -> (-215.3982, -162.6301)
  curve K17 (-215.559, -159.8841) -> (-214.8606, -160.9594)
  curve K18 (-216.5638, -159.6624) -> (-215.559, -159.8841)
  curve K19 (-217.5657, -160.3171) -> (-216.5638, -159.6624)
  curve K20 (-170.6699, -142.3161) -> (-170.5021, -143.5426)
  curve K21 (-170.4011, -141.2495) -> (-170.6699, -142.3161)
  curve K22 (-169.3748, -140.1009) -> (-170.4011, -141.2495)
  curve K23 (-168.077, -140.1206) -> (-169.3748, -140.1009)
  curve K24 (-167.4466, -140.6155) -> (-168.077, -140.1206)
  curve K25 (-167.1389, -141.3096) -> (-167.4466, -140.6155)
  curve K26 (-167.1342, -142.0862) -> (-167.1389, -141.3096)
  curve K27 (-167.3569, -142.9432) -> (-167.1342, -142.0862)
  curve K28 (-167.7647, -144.68) -> (-167.3569, -142.9432)
  curve K29 (-167.5329, -144.7899) -> (-167.7647, -144.68)
  curve K30 (-166.6472, -144.882) -> (-167.5329, -144.7899)
  curve K31 (-165.8859, -143.9973) -> (-166.6472, -144.882)
  curve K32 (-165.6889, -142.9643) -> (-165.8859, -143.9973)
  curve K33 (-166.2734, -142.1671) -> (-165.6889, -142.9643)
  line L55 (-165.761, -141.3443) -> (-166.2734, -142.1671)
  curve K34 (-165.0286, -142.145) -> (-165.761, -141.3443)
  curve K35 (-164.8507, -143.1756) -> (-165.0286, -142.145)
  curve K36 (-165.2019, -144.4594) -> (-164.8507, -143.1756)
  curve K37 (-165.8546, -145.4885) -> (-165.2019, -144.4594)
  curve K38 (-166.5345, -145.9312) -> (-165.8546, -145.4885)
  curve K39 (-167.2695, -145.9366) -> (-166.5345, -145.9312)
  curve K40 (-168.1162, -145.6108) -> (-167.2695, -145.9366)
  line L56 (-169.3113, -145.0751) -> (-168.1162, -145.6108)
  curve K41 (-170.918, -144.4236) -> (-169.3113, -145.0751)
  curve K42 (-171.6545, -144.3655) -> (-170.918, -144.4236)
  line L57 (-171.2348, -143.4294) -> (-171.6545, -144.3655)
  curve K43 (-170.5021, -143.5426) -> (-171.2348, -143.4294)
  curve K44 (-236.4141, -138.56) -> (-233.8745, -138.7564)
  curve K45 (-237.5395, -136.9883) -> (-236.4141, -138.56)
  curve K46 (-237.3306, -134.894) -> (-237.5395, -136.9883)
  curve K47 (-235.4632, -133.5636) -> (-237.3306, -134.894)
  curve K48 (-233.6794, -133.3966) -> (-235.4632, -133.5636)
  curve K49 (-232.4511, -134.0579) -> (-233.6794, -133.3966)
  curve K50 (-231.7211, -135.3037) -> (-232.4511, -134.0579)
  curve K51 (-231.9236, -137.4104) -> (-231.7211, -135.3037)
  curve K52 (-233.8745, -138.7564) -> (-231.9236, -137.4104)
  line L58 (-179.4176, -155.057) -> (-180.1077, -155.6522)
  line L59 (-174.1925, -161.1149) -> (-179.4176, -155.057)
  line L60 (-174.9364, -161.7565) -> (-174.1925, -161.1149)
  line L61 (-176.8004, -159.5953) -> (-174.9364, -161.7565)
  curve K53 (-177.4932, -161.2234) -> (-176.8004, -159.5953)
  curve K54 (-178.4006, -161.7213) -> (-177.4932, -161.2234)
  curve K55 (-179.3912, -161.7759) -> (-178.4006, -161.7213)
  curve K56 (-180.3718, -161.3785) -> (-179.3912, -161.7759)
  curve K57 (-181.2739, -160.6) -> (-180.3718, -161.3785)
  curve K58 (-182.2201, -158.375) -> (-181.2739, -160.6)
  curve K59 (-181.4123, -156.6045) -> (-182.2201, -158.375)
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  point P4 (-200, -120)
  point P41 (-200, -120)
  point P39 (-200, -120)
  point P44 (-200, -120)
  horizontal L17
  coincident P4 P41
  horizontal L19
  coincident P39 P44
  dimension "d481" diameter = 38
  dimension "d482" diameter = 49.4
  dimension "d483" angle L16 L17 = 45
  dimension "d484" angle L18 L19 = 45
extrude "Extrude13" add sketch "Sketch6" along normal blind 4
chamfer "Chamfer7" distance 3.7 Rotate Angle 40
chamfer "Chamfer8" distance 4 Rotate Angle 45
sketch "Suspension Pad" plane through (0, 0, 0) normal (0, 0, 1) x axis (1, 0, 0)
  line L1 (-120, 100) -> (-150, 100)
  line L2 (-120, -100) -> (-120, 100)
  line L3 (-150, -100) -> (-120, -100)
  line L4 (-150, 100) -> (-150, -100)
  line L5 (-165, 0) -> (-150, 0)
  line L6 (-105, 0) -> (-120, 0)
  curve K1 (-120, 100) -> (-120, -100)
  curve K2 (-150, -100) -> (-150, 100)
  line L7 (-135, -98) -> (-135, -100)
  line L8 (-135, 98) -> (-135, 100)
  line L9 (-150, 100) -> (-120, 0)
  line L10 (-150, -100) -> (-120, 0)
  line L11 (-125, 2) -> (-145, 2)
  line L12 (-125, -2) -> (-125, 2)
  line L13 (-145, -2) -> (-125, -2)
  line L14 (-145, 2) -> (-145, -2)
  line L15 (-125, -2) -> (-145, 2)
  line L16 (-145, -2) -> (-125, 2)
  line L17 (-125, 1) -> (-145, 1)
  line L18 (-125, -1) -> (-125, 1)
  line L19 (-145, -1) -> (-125, -1)
  line L20 (-145, 1) -> (-145, -1)
  line L21 (-125, -1) -> (-145, 1)
  line L22 (-145, -1) -> (-125, 1)
  line L23 (-125, 52) -> (-145, 52)
  line L24 (-125, 48) -> (-125, 52)
  line L25 (-145, 48) -> (-125, 48)
  line L26 (-145, 52) -> (-145, 48)
  line L27 (-125, 48) -> (-145, 52)
  line L28 (-145, 48) -> (-125, 52)
  line L29 (-125, 51) -> (-145, 51)
  line L30 (-125, 49) -> (-125, 51)
  line L31 (-145, 49) -> (-125, 49)
  line L32 (-145, 51) -> (-145, 49)
  line L33 (-125, 49) -> (-145, 51)
  line L34 (-145, 49) -> (-125, 51)
  line L35 (-125, -48) -> (-145, -48)
  line L36 (-125, -52) -> (-125, -48)
  line L37 (-145, -52) -> (-125, -52)
  line L38 (-145, -48) -> (-145, -52)
  line L39 (-125, -52) -> (-145, -48)
  line L40 (-145, -52) -> (-125, -48)
  line L41 (-125, -49) -> (-145, -49)
  line L42 (-125, -51) -> (-125, -49)
  line L43 (-145, -51) -> (-125, -51)
  line L44 (-145, -49) -> (-145, -51)
  line L45 (-125, -51) -> (-145, -49)
  line L46 (-145, -51) -> (-125, -49)
  circle C1 centre (-135, -96.5) radius 1.5
  circle C2 centre (-135, 96.5) radius 1.5
  point P6 (-150, 0)
  point P8 (-120, 0)
  point P10 (-135, -100)
  point P11 (-135, -98)
  point P13 (-135, 100)
  point P14 (-135, 98)
  point P20 (-135, 0)
  point P25 (-135, 0)
  point P30 (-135, 50)
  point P35 (-135, 50)
  point P40 (-135, -50)
  point P45 (-135, -50)
  point P2 (-150, 100)
  point P3 (-120, 100)
  point P5 (-150, -100)
  point P7 (-165, 0)
  point P9 (-105, 0)
  point P18 (-125, -2)
  point P19 (-145, -2)
  point P17 (-125, 2)
  point P22 (-125, 1)
  point P23 (-125, -1)
  point P28 (-125, 48)
  point P29 (-145, 48)
  point P27 (-125, 52)
  point P32 (-125, 51)
  point P33 (-125, 49)
  point P38 (-125, -52)
  point P39 (-145, -52)
  point P37 (-125, -48)
  point P43 (-125, -51)
  point P44 (-145, -51)
  point P42 (-125, -49)
  horizontal L1
  vertical L2
  horizontal L3
  vertical L4
  midpoint L4 P6
  perpendicular L4 L5
  midpoint L2 P8
  perpendicular L2 L6
  midpoint L3 P10
  perpendicular L3 L7
  coincident P11 C1
  midpoint L1 P13
  perpendicular L1 L8
  coincident P14 C2
  horizontal L11
  perpendicular L11 L12
  parallel L11 L13
  parallel L12 L14
  coincident L15 P20
  coincident L16 P20
  horizontal L17
  perpendicular L17 L18
  parallel L17 L19
  parallel L18 L20
  coincident L21 P25
  coincident L22 P25
  coincident P20 P25
  horizontal L23
  perpendicular L23 L24
  parallel L23 L25
  parallel L24 L26
  coincident L27 P30
  coincident L28 P30
  midpoint L9 P30
  horizontal L29
  perpendicular L29 L30
  parallel L29 L31
  parallel L30 L32
  coincident L33 P35
  coincident L34 P35
  coincident P30 P35
  horizontal L35
  perpendicular L35 L36
  parallel L35 L37
  parallel L36 L38
  coincident L39 P40
  coincident L40 P40
  midpoint L10 P40
  horizontal L41
  perpendicular L41 L42
  parallel L41 L43
  parallel L42 L44
  coincident L45 P45
  coincident L46 P45
  coincident P40 P45
  dimension "d491" distance P2 P3 = 30
  dimension "d492" distance P2 P5 = 200
  dimension "d493" distance P6 P7 = 15
  dimension "d494" distance P8 P9 = 15
  dimension "d495" distance P10 P11 = 2
  dimension "d496" diameter C1 = 3
  dimension "d497" distance P13 P14 = 2
  dimension "d498" diameter C2 = 3
  dimension "d499" distance P18 P19 = 20
  dimension "d500" distance P17 P18 = 4
  dimension "d501" distance P22 P23 = 2
  dimension "d502" distance P28 P29 = 20
  dimension "d503" distance P27 P28 = 4
  dimension "d504" distance P32 P33 = 2
  dimension "d505" distance P38 P39 = 20
  dimension "d506" distance P37 P38 = 4
  dimension "d507" distance P43 P44 = 20
  dimension "d508" distance P42 P43 = 2
extrude "Extrude5" new body sketch "Suspension Pad" profile of L1 L3 K1 K2 L7 C1 L8 C2 L11 L12 L13 L14 L17 L18 L19 L20 L23 L24 L25 L26 L29 L30 L31 L32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 along normal blind 1.5 bodies "TPU Suspension Pad"
sketch "45cm 1.75mm TPU" plane through (0, 0, 0) normal (0, 0, 1) x axis (1, 0, 0)
  line L1 (-98.25, 180) -> (-100, 180)
  line L2 (-98.25, -270) -> (-98.25, 180)
  line L3 (-100, -270) -> (-98.25, -270)
  line L4 (-100, 180) -> (-100, -270)
  point P2 (-100, 180)
  point P3 (-98.25, 180)
  point P5 (-100, -270)
  horizontal L1
  vertical L2
  horizontal L3
  vertical L4
  dimension "d511" distance P2 P3 = 1.75
  dimension "d512" distance P2 P5 = 450
extrude "Extrude6" new body sketch "45cm 1.75mm TPU" along normal blind 1.75 bodies "45cm 1.75mm Unprinted TPU"
fillet "Fillet1" radius 0.875 (= "( 1.75 / 2 ) * 1 mm")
